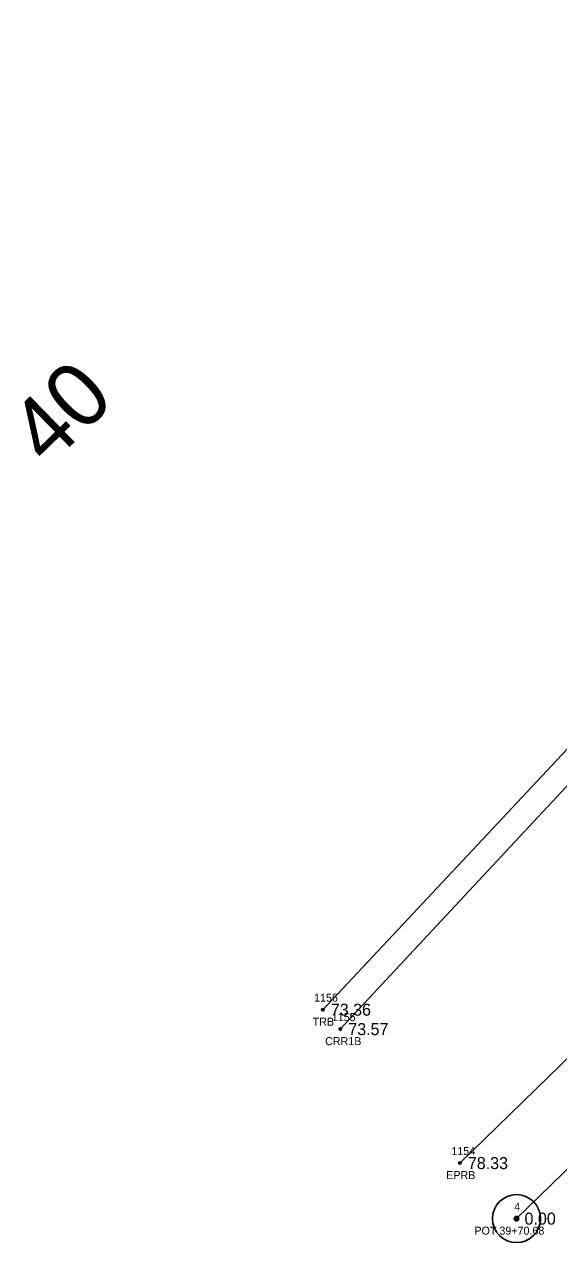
# Model space of a CAD drawing. Extents: x 2505249 to 2506333, y 912937 to 914171.
# Drawn here: x 2505301.8 to 2505368.6, y 913045.4 to 913197.6 of the extents above; entities that cross this region are included whole.
import ezdxf

# ---------------------------------------------------------------- set-up
doc = ezdxf.new("R2010")
doc.units = 0
for name, color, linetype in [('RD_EX_H2O', 7, 'Continuous'), ('RD_EX_H2O_txCode', 7, 'Continuous'), ('RD_EX_Road', 7, 'Continuous'), ('RD_EX_Road_txCode', 7, 'Continuous'), ('RD_EX_TX_H2O_ELEV', 7, 'Continuous'), ('RD_EX_TX_Road_ELEV', 7, 'Continuous'), ('RD_EX_TX_VEG_ELEV', 7, 'Continuous'), ('RD_EX_VEG', 7, 'Continuous'), ('RD_EX_VEG_txCode', 7, 'Continuous'), ('RD_HC_Cl', 7, 'Continuous'), ('RD_HC_Data', 7, 'Continuous'), ('RD_HC_Survey_ELEV', 7, 'Continuous'), ('RD_HC_TX_Sta50', 7, 'Continuous'), ('RD_HC_txCode', 7, 'Continuous'), ('RD_SMD_Locator', 7, 'Continuous')]:
    doc.layers.add(name, color=color, linetype=linetype)

msp = doc.modelspace()

# ---------------------------------------------------------------- linework, layer by layer
at = {"layer": 'RD_EX_H2O'}
msp.add_lwpolyline([(2505789.47, 913464.31), (2505758.18, 913486.1), (2505736.66, 913480.49), (2505719.32, 913463.86), (2505699.9, 913439.21), (2505669.03, 913402.75), (2505628.5, 913357.9), (2505593, 913316.39), (2505556.58, 913279.8), (2505487.72, 913211.38), (2505413.81, 913149.81), (2505341.31, 913072.1)], dxfattribs=at)
at = {"layer": 'RD_EX_Road'}
msp.add_lwpolyline([(2505758.23, 913470.96), (2505754.11, 913462.85), (2505725.4, 913427.85), (2505690.77, 913387.11), (2505650.25, 913343.36), (2505607.72, 913300.12), (2505570.97, 913264.99), (2505501.53, 913196.72), (2505431.76, 913128.83), (2505356.25, 913055.37)], dxfattribs=at)
at = {"layer": 'RD_EX_VEG'}
msp.add_lwpolyline([(2506002.64, 913815.25), (2505883.7, 913669.64), (2505827.83, 913593.29), (2505814.43, 913589.15), (2505792.49, 913560.55), (2505725.64, 913468.24), (2505664.37, 913399.09), (2505478.33, 913221), (2505411.99, 913152.19), (2505339.13, 913074.53)], dxfattribs=at)
at = {"layer": 'RD_HC_Cl'}
msp.add_line((2505363.33, 913048.43), (2505609.42, 913288.1), dxfattribs=at)
at = {"layer": 'RD_HC_Data'}
for radius in [3, 0.282]:
    msp.add_circle((2505363.33, 913048.43), radius, dxfattribs=at)
at = {"layer": 'RD_SMD_Locator'}
for centre in [(2505339.13, 913074.53), (2505341.31, 913072.1), (2505356.25, 913055.37), (2505363.33, 913048.43)]:
    msp.add_circle(centre, 0.15, dxfattribs=at)

# ---------------------------------------------------------------- texts
at = {"layer": 'RD_EX_H2O_txCode'}
for s, p in [('1155', (2505340.25, 913073.1)), ('CRR1B', (2505339.42, 913070.1))]:
    msp.add_text(s, height=1, dxfattribs=at).set_placement(p)
at = {"layer": 'RD_EX_Road_txCode'}
for s, p in [('1154', (2505355.19, 913056.37)), ('EPRB', (2505354.55, 913053.37))]:
    msp.add_text(s, height=1, dxfattribs=at).set_placement(p)
at = {"layer": 'RD_EX_TX_H2O_ELEV'}
msp.add_text('73.57', height=1.5, dxfattribs=at).set_placement((2505342.31, 913071.35))
at = {"layer": 'RD_EX_TX_Road_ELEV'}
msp.add_text('78.33', height=1.5, dxfattribs=at).set_placement((2505357.25, 913054.62))
at = {"layer": 'RD_EX_TX_VEG_ELEV'}
msp.add_text('73.36', height=1.5, dxfattribs=at).set_placement((2505340.13, 913073.78))
at = {"layer": 'RD_EX_VEG_txCode'}
for s, p in [('1156', (2505338.04, 913075.53)), ('TRB', (2505337.86, 913072.53))]:
    msp.add_text(s, height=1, dxfattribs=at).set_placement(p)
at = {"layer": 'RD_HC_Survey_ELEV'}
msp.add_text('0.00', height=1.5, dxfattribs=at).set_placement((2505364.33, 913047.68))
at = {"layer": 'RD_HC_TX_Sta50'}
msp.add_text('40', height=8, rotation=44.2421, dxfattribs=at).set_placement((2505304.83, 913142.22))
at = {"layer": 'RD_HC_txCode'}
for s, p in [('4', (2505363.04, 913049.43)), ('POT 39+70.68', (2505358.07, 913046.43))]:
    msp.add_text(s, height=1, dxfattribs=at).set_placement(p)

doc.saveas('drawing.dxf')
